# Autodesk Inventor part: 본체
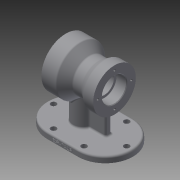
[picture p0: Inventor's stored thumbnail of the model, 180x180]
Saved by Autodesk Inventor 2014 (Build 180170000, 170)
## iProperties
Created: 2020-01
Part Number: 본체
Material: Generic
Document SubType Name: Modeling
Designer: kh
Density: 1 g/cm^3
Appearance: Default
Author: kh
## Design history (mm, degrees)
sketch "Sketch1"
  geometry: L1 (-25, 0)-(25, 0); L2 (-25, -45)-(25, -45); L3 (25, 45)-(-25, 45); L4 (25, 35)-(-25, 35); L5 (-25, -35)-(25, -35); C1 r 4.5 at (-25, 35); C2 r 4.5 at (-60, 0); C3 r 4.5 at (-25, -35); C4 r 4.5 at (60, 0); C5 r 4.5 at (25, 35); C6 r 4.5 at (25, -35); A1 r 45 centre (-25, 0) between (-25, 45) and (-25, -45); A2 r 45 centre (25, 0) between (25, -45) and (25, 45); A3 r 35 centre (-25, 0) between (-25, 35) and (-25, -35); A4 r 35 centre (25, 0) between (25, -35) and (25, 35); 1 further point
  constraints: 12 end point, 10 centre point, 10 point on circle, 4 coincident, 4 tangent, 2 parallel, 1 horizontal, 1 midpoint, 3 other
  dimensions: "d0" = 50 distance of L1.end L1.start; "d1" = 45 radius of A1; "d2" = 10 distance between parallel lines of L2 L5; "d3" = 9 diameter of C1; "d4" = 9 diameter of C2 (= d3); "d5" = 9 diameter of C3 (= d4); "d7" = 9 diameter of C4 (= d6); "d8" = 9 diameter of C5 (= d7); "d9" = 9 diameter of C6
extrude "Extrusion1" new body sketch "Sketch1" distance "d10" = 10; taper "d11" = 0 deg
sketch "Sketch2"
  geometry: L1 (40, 80)-(40, 120); L2 (40, 120)-(16, 120); L3 (16, 120)-(1.103, 107.5); L4 (1.103, 107.5)-(-13.289, 107.5); L5 (-13.289, 107.5)-(-24, 115); L6 (-24, 115)-(-40, 115); L7 (-40, 115)-(-40, 80); L8 (-40, 80)-(40, 80); L9 (70, 0)-(70, 10) reference; L10 (40, 106)-(20, 106); L11 (20, 106)-(20, 96); L12 (20, 96)-(-23, 96); L13 (-23, 96)-(-23, 100); L14 (-23, 100)-(-40, 100); 1 further point
  constraints: 26 end point, 5 parallel, 5 perpendicular, 2 point on line, 1 vertical
  dimensions: "d12" = 80 vertical distance of L7.end point (0, 0); "d13" = 30 distance between parallel lines of L1 L9; "d14" = 80 horizontal distance of L6.end L1.end; "d15" = 80 diameter of L2 L8; "d16" = 24 distance of L1.end L2.end; "d18" = 40 deg angle of L4 L3; "d19" = 35 deg angle of L4 L5; "d20" = 16 distance of L5.end L6.end; "d21" = 70 diameter of L6 L8; "d22" = 55 diameter of L4 L8; "d23" = 20 distance of L10.start L10.end; "d24" = 17 distance of L13.end L14.end; "d25" = 52 diameter of L10 L8; "d26" = 40 diameter of L14 L8; "d27" = 32 diameter of L12 L8
revolve "Revolution1" sketch "Sketch2" stored, may be unused: angle "d28" = 90 deg
sketch "Sketch3"
  geometry: L1 (-5.981, -5)-(30, -5); L2 (30, -5)-(30, 5); L3 (30, 5)-(-5.981, 5); L4 (-5.981, 5)-(-5.981, -5); L5 (-5.981, -5)-(30, 5); L6 (30, -5)-(-5.981, 5); L7 (-60, 0)-(-70, 0); L8 (40, 35)-(40, -35) reference; C1 r 4.5 at (-60, 0) reference; C2 r 16 at (-12, 0); A1 r 45 centre (-25, 0) between (-25, 45) and (-25, -45) reference; 3 further points
  constraints: 14 end point, 3 midpoint, 2 horizontal alignment, 2 parallel, 2 perpendicular, 1 centre point, 1 horizontal, 1 point on circle
  dimensions: "d29" = 58 distance of C2.centre L7.end; "d30" = 16 radius of C2; "d31" = 10 distance between parallel lines of L1 L3; "d32" = 10 distance between parallel lines of L2 L8
extrude "Extrusion2" join sketch "Sketch3" stored distance "d33" = 10; taper "d34" = 0 deg
sketch "Sketch4"
  geometry: C1 r 20 at (0, 0) reference; 2 further points
  constraints: 1 horizontal alignment
  dimensions: "d35" = 27.5 distance of C1.centre point (-27.5, 0)
hole "Hole1" sketch "Sketch4" at (-27.5, 0) diameter "d36" = 3.459; stored, may be unused: countersink angle "d40" = 90 deg, drill point angle "d42" = 118 deg; dims "d37" = 9, "d38" = 4, "d39" = 2, "d41" = 11
pattern_circular "Circular Pattern1" dims angle "d44" = 360 deg
sketch "Sketch5"
  geometry: C1 r 40 at (0, 0) reference; 2 further points
  constraints: 1 horizontal alignment
  dimensions: "d46" = 33 distance of point (33, 0) C1.centre
hole "Hole2" sketch "Sketch5" at (33, 0) diameter "d47" = 3.459; stored, may be unused: countersink angle "d51" = 90 deg, drill point angle "d53" = 118 deg; dims "d48" = 9, "d49" = 4, "d50" = 2, "d52" = 11
pattern_circular "Circular Pattern2" dims angle "d55" = 360 deg
sketch "Sketch6"
  geometry: L1 (0, 0)-(50, 0) reference; L2 (-45, 0)-(-45, 10) reference; 3 further points
  constraints: 1 midpoint, 1 other
  dimensions: "d57" = 4 distance of point (25, 4) point (25, 0); "d68" = 70 distance from line of L2 point (25, 4)
emboss "Emboss1" sketch "Sketch6" dims "d0" = 50, "d1" = 45, "d2" = 10, "d3" = 9, "d4" = 9 (= d3), "d5" = 9 (= d4), "d7" = 9 (= d6), "d8" = 9 (= d7), "d9" = 9, "d58" = 0.5, "d59" = 0
fillet "Fillet1" dims "d60" = 0.3, "d61" = 3
fillet "Fillet2" dims "d62" = 3
fillet "Fillet3" dims "d63" = 3
chamfer "Chamfer1" distance "d64" = 1; stored, may be unused: second distance "d65" = 2, angle "d66" = 45 deg
body "Solid1"
other parameters: "d6" = 9 (= d5)
